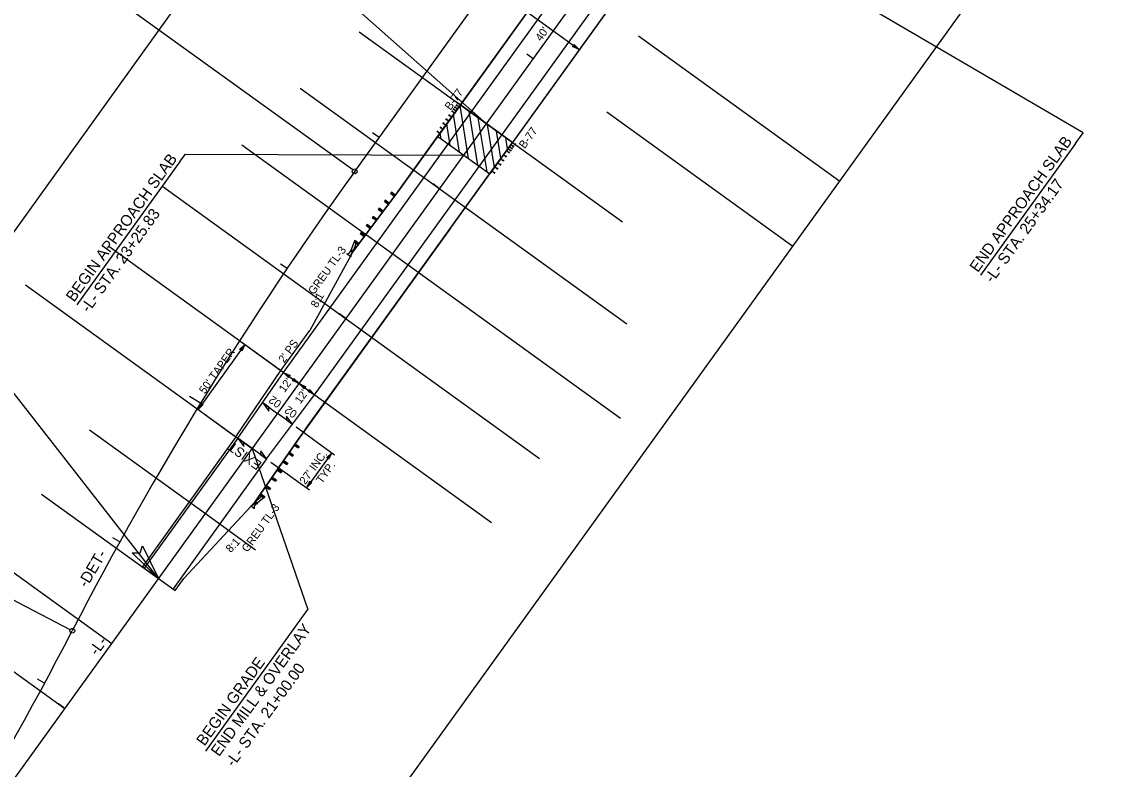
# Model space of a CAD drawing. Extents: x 2189281 to 2191267, y 386656 to 389012.
# Drawn here: x 2190029 to 2190710, y 387465 to 387932 of the extents above; entities that cross this region are included whole.
import ezdxf

# ---------------------------------------------------------------- set-up
doc = ezdxf.new("R2010")
doc.units = 0
for name, color, linetype in [('Prop Approach Slab', 7, 'Continuous'), ('Prop Approach Slab Hatching', 7, 'Continuous'), ('Prop Conc Shoulder Berm Gutter', 7, 'Continuous'), ('Prop Dimension', 7, 'Continuous'), ('Prop Dimension Text', 7, 'Continuous'), ('Prop DSN Text', 7, 'Continuous'), ('Prop EOT', 7, 'Continuous'), ('Prop Guardrail', 7, 'Continuous'), ('Prop Guardrail Anchor Unit CELL', 7, 'Continuous'), ('Prop Horizontal Alignment', 7, 'Continuous'), ('Prop Horizontal Alignment Station Label', 7, 'Continuous'), ('Prop Horizontal Alignment Tick Large', 7, 'Continuous'), ('Prop Horizontal Alignment Tick Small', 7, 'Continuous'), ('Prop Paved Shoulder', 7, 'Continuous'), ('Prop Roadway Bridge', 7, 'Continuous'), ('Prop Structure Anchor Unit CELL', 7, 'Continuous'), ('Prop Superelevation  Arrow CELL', 7, 'Continuous'), ('Prop Superelevation Label', 7, 'Continuous'), ('Prop Terminator CELL', 7, 'Continuous'), ('Scratch_Level_5', 7, 'Continuous'), ('Scratch_Level_6', 7, 'Continuous')]:
    doc.layers.add(name, color=color, linetype=linetype)

msp = doc.modelspace()

# ---------------------------------------------------------------- linework, layer by layer
at = {"layer": 'Prop Approach Slab'}
msp.add_lwpolyline([(2190302.81, 387879.77), (2190288.67, 387860.16), (2190321.11, 387836.77), (2190335.25, 387856.37)], close=True, dxfattribs=at)
at = {"layer": 'Prop Approach Slab Hatching'}
for p, q in [((2190307.96, 387846.25), (2190302.58, 387879.46)), ((2190302.23, 387850.38), (2190298.45, 387873.72)), ((2190313.7, 387842.11), (2190308.23, 387875.85)), ((2190319.43, 387837.98), (2190313.97, 387871.72)), ((2190290.76, 387858.66), (2190290.18, 387862.25)), ((2190296.49, 387854.52), (2190294.31, 387867.99)), ((2190324.04, 387840.82), (2190319.7, 387867.58)), ((2190328.17, 387846.56), (2190325.44, 387863.45)), ((2190332.31, 387852.29), (2190331.17, 387859.31))]:
    msp.add_line(p, q, dxfattribs=at)
at = {"layer": 'Prop Conc Shoulder Berm Gutter'}
for p, q in [((2190264.19, 387826.23), (2190288.67, 387860.16)), ((2190206.57, 387677.93), (2190321.11, 387836.77))]:
    msp.add_line(p, q, dxfattribs=at)
at = {"layer": 'Prop Dimension'}
for p, q in [((2190344.62, 387937.74), (2190377.06, 387914.35)), ((2190168.2, 387730.25), (2190138.96, 387689.7)), ((2190166.44, 387731.53), (2190190.07, 387714.48)), ((2190192.31, 387712.87), (2190211.78, 387698.83)), ((2190138.23, 387690.23), (2190161.39, 387673.52)), ((2190200.21, 387678.81), (2190224.26, 387661.47)), ((2190222.51, 387662.74), (2190206.71, 387640.84)), ((2190184.42, 387656.91), (2190208.46, 387639.57))]:
    msp.add_line(p, q, dxfattribs=at)
at = {"layer": 'Prop DSN Text'}
for p, q in [((2190687.03, 387855.75), (2190627.74, 387773.54)), ((2190127.87, 387844.59), (2190063.28, 387755.03)), ((2190114.3, 387584.19), (2189951.78, 387791.94)), ((2190172.8, 387665.3), (2190207.49, 387564.83)), ((2190143.55, 387624.74), (2190174.85, 387602.17)), ((2190143.71, 387476.39), (2190207.49, 387564.83))]:
    msp.add_line(p, q, dxfattribs=at)
for points in [[(2190687.03, 387855.75), (2190691.85, 387862.42), (2190426.76, 388017.45)], [(2190204.99, 387981.41), (2190199.63, 387973.98), (2190319.03, 387868.07)], [(2190127.87, 387844.59), (2190131.05, 387849), (2190304.89, 387848.46)]]:
    msp.add_lwpolyline(points, dxfattribs=at)
at = {"layer": 'Prop EOT'}
for p, q in [((2190192.31, 387712.87), (2190484.78, 388118.41)), ((2190163.83, 387671.76), (2190192.31, 387712.87)), ((2190163.83, 387671.76), (2190105.39, 387590.62)), ((2190181.76, 387658.83), (2190162.56, 387672.68)), ((2190172.8, 387665.3), (2190172.8, 387665.3)), ((2190181.76, 387658.83), (2190123.31, 387577.7)), ((2190104.17, 387591.49), (2190124.72, 387576.68))]:
    msp.add_line(p, q, dxfattribs=at)
msp.add_lwpolyline([(2190181.76, 387658.83), (2190211.78, 387698.83), (2190504.24, 388104.37), (2190532.84, 388145.39)], dxfattribs=at)
at = {"layer": 'Prop Guardrail'}
msp.add_line((2190335.25, 387856.37), (2190335.26, 387856.36), dxfattribs=at)
for points in [[(2190289.43, 387861.21), (2190263.67, 387825.52)], [(2190201.05, 387670.29), (2190320.63, 387836.09), (2190321.87, 387837.82)]]:
    msp.add_lwpolyline(points, dxfattribs=at)
at = {"layer": 'Prop Guardrail Anchor Unit CELL'}
for p, q in [((2190263.67, 387825.52), (2190235.57, 387788.15)), ((2190259.75, 387825.29), (2190259.15, 387824.49)), ((2190261.54, 387822.69), (2190259.15, 387824.49)), ((2190259.15, 387824.49), (2190260.94, 387824.39)), ((2190262.14, 387823.49), (2190259.75, 387825.29)), ((2190260.34, 387823.59), (2190259.75, 387825.29)), ((2190260.94, 387824.39), (2190260.34, 387823.59)), ((2190261.54, 387822.69), (2190260.34, 387823.59)), ((2190260.34, 387823.59), (2190262.14, 387823.49)), ((2190260.94, 387824.39), (2190261.54, 387822.69)), ((2190262.14, 387823.49), (2190261.54, 387822.69)), ((2190252.13, 387815.25), (2190251.53, 387814.45)), ((2190254.57, 387813.41), (2190252.13, 387815.25)), ((2190252.75, 387813.53), (2190252.13, 387815.25)), ((2190255.92, 387820.29), (2190255.32, 387819.49)), ((2190257.76, 387817.65), (2190255.32, 387819.49)), ((2190255.32, 387819.49), (2190257.14, 387819.37)), ((2190258.36, 387818.45), (2190255.92, 387820.29)), ((2190256.54, 387818.57), (2190255.92, 387820.29)), ((2190257.14, 387819.37), (2190256.54, 387818.57)), ((2190258.36, 387818.45), (2190256.54, 387818.57)), ((2190257.14, 387819.37), (2190257.76, 387817.65)), ((2190248.36, 387810.2), (2190247.76, 387809.4)), ((2190250.18, 387807.58), (2190247.76, 387809.4)), ((2190247.76, 387809.4), (2190249.57, 387809.29)), ((2190250.78, 387808.38), (2190248.36, 387810.2)), ((2190248.97, 387808.49), (2190248.36, 387810.2)), ((2190249.57, 387809.29), (2190248.97, 387808.49)), ((2190250.78, 387808.38), (2190248.97, 387808.49)), ((2190249.57, 387809.29), (2190250.18, 387807.58)), ((2190250.78, 387808.38), (2190250.18, 387807.58)), ((2190253.97, 387812.62), (2190251.53, 387814.45)), ((2190251.53, 387814.45), (2190253.35, 387814.33)), ((2190253.35, 387814.33), (2190252.75, 387813.53)), ((2190254.57, 387813.41), (2190252.75, 387813.53)), ((2190253.35, 387814.33), (2190253.97, 387812.62)), ((2190244.49, 387805.23), (2190243.89, 387804.43)), ((2190246.39, 387802.54), (2190243.89, 387804.43)), ((2190243.89, 387804.43), (2190245.74, 387804.29)), ((2190247, 387803.34), (2190244.49, 387805.23)), ((2190245.14, 387803.49), (2190244.49, 387805.23)), ((2190245.74, 387804.29), (2190245.14, 387803.49)), ((2190247, 387803.34), (2190245.14, 387803.49)), ((2190245.74, 387804.29), (2190246.39, 387802.54)), ((2190236.37, 387794.31), (2190234.67, 387789.46)), ((2190236.97, 387795.11), (2190236.37, 387794.31)), ((2190238.82, 387792.47), (2190236.37, 387794.31)), ((2190236.37, 387794.31), (2190238.2, 387794.19)), ((2190239.42, 387793.27), (2190236.97, 387795.11)), ((2190237.59, 387793.39), (2190236.97, 387795.11)), ((2190238.2, 387794.19), (2190237.59, 387793.39)), ((2190238.2, 387794.19), (2190238.82, 387792.47)), ((2190240.81, 387800.11), (2190240.21, 387799.31)), ((2190242.61, 387797.51), (2190240.21, 387799.31)), ((2190240.21, 387799.31), (2190242.01, 387799.21)), ((2190243.21, 387798.31), (2190240.81, 387800.11)), ((2190241.41, 387798.41), (2190240.81, 387800.11)), ((2190242.01, 387799.21), (2190241.41, 387798.41)), ((2190243.21, 387798.31), (2190241.41, 387798.41)), ((2190242.01, 387799.21), (2190242.61, 387797.51)), ((2190233.3, 387787.23), (2190234.5, 387788.89)), ((2190234.67, 387789.46), (2190234.07, 387788.66)), ((2190235.27, 387787.75), (2190234.07, 387788.66)), ((2190234.07, 387788.66), (2190235.87, 387788.55)), ((2190235.49, 387788.17), (2190234.29, 387786.52)), ((2190234.67, 387789.46), (2190234.37, 387789.06)), ((2190234.5, 387788.89), (2190235, 387788.53)), ((2190235.87, 387788.55), (2190234.67, 387789.46)), ((2190235.27, 387787.75), (2190234.67, 387789.46)), ((2190235, 387788.53), (2190235.49, 387788.17)), ((2190237.59, 387793.39), (2190235.87, 387788.55)), ((2190239.42, 387793.27), (2190237.59, 387793.39)), ((2190231.92, 387786.78), (2190233.3, 387787.23)), ((2190234.3, 387785.06), (2190231.92, 387786.78)), ((2190234.29, 387786.52), (2190234.3, 387785.06)), ((2190201.05, 387670.29), (2190174.46, 387631.84)), ((2190199.6, 387668.2), (2190199.03, 387667.38)), ((2190199.03, 387667.38), (2190201.5, 387665.67)), ((2190199.03, 387667.38), (2190200.26, 387666.53)), ((2190200.83, 387667.35), (2190199.03, 387667.38)), ((2190199.6, 387668.2), (2190202.07, 387666.5)), ((2190200.26, 387666.53), (2190199.6, 387668.2)), ((2190200.83, 387667.35), (2190200.26, 387666.53)), ((2190200.26, 387666.53), (2190202.07, 387666.5)), ((2190201.5, 387665.67), (2190200.83, 387667.35)), ((2190202.07, 387666.5), (2190201.5, 387665.67)), ((2190195.45, 387662.2), (2190197.96, 387660.46)), ((2190197.27, 387662.15), (2190195.45, 387662.2)), ((2190196.02, 387663.02), (2190198.53, 387661.28)), ((2190196.02, 387663.02), (2190196.7, 387661.33)), ((2190197.27, 387662.15), (2190196.7, 387661.33)), ((2190196.7, 387661.33), (2190198.53, 387661.28)), ((2190197.96, 387660.46), (2190197.27, 387662.15)), ((2190198.53, 387661.28), (2190197.96, 387660.46)), ((2190188.85, 387652.65), (2190188.28, 387651.83)), ((2190188.28, 387651.83), (2190190.78, 387650.1)), ((2190190.1, 387651.79), (2190188.28, 387651.83)), ((2190188.85, 387652.65), (2190191.35, 387650.93)), ((2190188.85, 387652.65), (2190189.53, 387650.97)), ((2190190.1, 387651.79), (2190189.53, 387650.97)), ((2190190.78, 387650.1), (2190190.1, 387651.79)), ((2190191.86, 387657.01), (2190194.37, 387655.28)), ((2190193.69, 387656.97), (2190191.86, 387657.01)), ((2190192.43, 387657.84), (2190194.94, 387656.1)), ((2190192.43, 387657.84), (2190193.12, 387656.15)), ((2190193.69, 387656.97), (2190193.12, 387656.15)), ((2190193.12, 387656.15), (2190194.94, 387656.1)), ((2190194.37, 387655.28), (2190193.69, 387656.97)), ((2190194.94, 387656.1), (2190194.37, 387655.28)), ((2190184.7, 387646.65), (2190187.28, 387644.86)), ((2190186.56, 387646.58), (2190184.7, 387646.65)), ((2190185.27, 387647.47), (2190187.85, 387645.69)), ((2190185.27, 387647.47), (2190185.99, 387645.76)), ((2190186.56, 387646.58), (2190185.99, 387645.76)), ((2190185.99, 387645.76), (2190187.85, 387645.69)), ((2190187.28, 387644.86), (2190186.56, 387646.58)), ((2190187.85, 387645.69), (2190187.28, 387644.86)), ((2190189.53, 387650.97), (2190191.35, 387650.93)), ((2190191.35, 387650.93), (2190190.78, 387650.1)), ((2190181.12, 387641.46), (2190183.58, 387639.76)), ((2190182.92, 387641.43), (2190181.12, 387641.46)), ((2190181.68, 387642.29), (2190184.15, 387640.58)), ((2190181.68, 387642.29), (2190182.35, 387640.61)), ((2190182.92, 387641.43), (2190182.35, 387640.61)), ((2190182.35, 387640.61), (2190184.15, 387640.58)), ((2190183.58, 387639.76), (2190182.92, 387641.43)), ((2190184.15, 387640.58), (2190183.58, 387639.76)), ((2190174.5, 387631.77), (2190173.31, 387630.11)), ((2190174.18, 387631.43), (2190175.41, 387630.57)), ((2190174.18, 387631.43), (2190175.98, 387631.4)), ((2190174.3, 387629.39), (2190175.5, 387631.06)), ((2190175, 387631.41), (2190174.5, 387631.77)), ((2190178.79, 387635.41), (2190174.75, 387632.25)), ((2190174.75, 387632.25), (2190175.98, 387631.4)), ((2190175.41, 387630.57), (2190174.75, 387632.25)), ((2190175.5, 387631.06), (2190175, 387631.41)), ((2190175.98, 387631.4), (2190175.41, 387630.57)), ((2190175.98, 387631.4), (2190175.69, 387630.98)), ((2190180.05, 387634.54), (2190175.98, 387631.4)), ((2190177.53, 387636.28), (2190180.05, 387634.54)), ((2190179.36, 387636.23), (2190177.53, 387636.28)), ((2190178.1, 387637.1), (2190180.62, 387635.36)), ((2190178.1, 387637.1), (2190178.79, 387635.41)), ((2190179.36, 387636.23), (2190178.79, 387635.41)), ((2190178.79, 387635.41), (2190180.62, 387635.36)), ((2190180.05, 387634.54), (2190179.36, 387636.23)), ((2190180.62, 387635.36), (2190180.05, 387634.54)), ((2190173.31, 387630.11), (2190171.92, 387629.65)), ((2190171.92, 387629.65), (2190174.31, 387627.94)), ((2190174.31, 387627.94), (2190174.3, 387629.39))]:
    msp.add_line(p, q, dxfattribs=at)
at = {"layer": 'Prop Horizontal Alignment'}
for p, q in [((2189529.37, 386773.11), (2190699.23, 388395.27)), ((2190236.81, 387838.31), (2190392.46, 388054.13))]:
    msp.add_line(p, q, dxfattribs=at)
for centre, start, end in [((2192102.3, 386492.96), 144.20184, 152.59586), ((2188018.5, 388610.18), 324.20184, 332.59586)]:
    msp.add_arc(centre, 2300, start, end, dxfattribs=at)
at = {"layer": 'Prop Horizontal Alignment Station Label'}
for p, q in [((2190235.59, 387839.18), (2190080.89, 387950.75)), ((2190059.07, 387552.26), (2189924.38, 387622.09))]:
    msp.add_line(p, q, dxfattribs=at)
for centre in [(2190236.81, 387838.31), (2190060.4, 387551.57)]:
    msp.add_circle(centre, 1.5, dxfattribs=at)
at = {"layer": 'Prop Horizontal Alignment Tick Large'}
for p, q in [((2190140.51, 387693.54), (2190133.69, 387697.71)), ((2190114.3, 387584.19), (2190107.81, 387588.87))]:
    msp.add_line(p, q, dxfattribs=at)
at = {"layer": 'Prop Horizontal Alignment Tick Small'}
for p, q in [((2190348.28, 387908.62), (2190344.22, 387911.55)), ((2190252.07, 387859.46), (2190248.01, 387862.39)), ((2190289.78, 387827.51), (2190285.73, 387830.44)), ((2190194.55, 387777.67), (2190190.4, 387780.46)), ((2190231.29, 387746.41), (2190227.23, 387749.33)), ((2190172.8, 387665.3), (2190168.74, 387668.22)), ((2190090.18, 387607.13), (2190085.81, 387609.56)), ((2190043.13, 387518.9), (2190038.73, 387521.27)), ((2190055.81, 387503.08), (2190051.75, 387506.01))]:
    msp.add_line(p, q, dxfattribs=at)
at = {"layer": 'Prop Paved Shoulder'}
for p, q in [((2190411.02, 388029.82), (2190288.67, 387860.16)), ((2190443.46, 388006.42), (2190321.11, 387836.77)), ((2190264.19, 387826.23), (2190235.57, 387788.15)), ((2190235.57, 387788.15), (2190208.71, 387739.03)), ((2190162.56, 387672.68), (2190137.23, 387637.3)), ((2190137.23, 387637.3), (2190104.17, 387591.49)), ((2190174.46, 387631.84), (2190130.07, 387584.11)), ((2190124.72, 387576.68), (2190130.07, 387584.11))]:
    msp.add_line(p, q, dxfattribs=at)
for points in [[(2190296.64, 387802.83), (2190201.05, 387670.29), (2190174.46, 387631.84)], [(2190162.56, 387672.68), (2190190.69, 387714.04), (2190208.71, 387739.03)]]:
    msp.add_lwpolyline(points, dxfattribs=at)
at = {"layer": 'Prop Roadway Bridge'}
msp.add_lwpolyline([(2190302.81, 387879.77), (2190396.4, 388009.54), (2190428.84, 387986.14), (2190335.25, 387856.37)], close=True, dxfattribs=at)
at = {"layer": 'Prop Structure Anchor Unit CELL'}
for p, q in [((2190302.81, 387879.77), (2190289.43, 387861.21)), ((2190297.86, 387876.33), (2190297.19, 387875.4)), ((2190298.78, 387877.6), (2190298.11, 387876.67)), ((2190300.07, 387875.97), (2190298.44, 387877.14)), ((2190299.69, 387878.87), (2190299.02, 387877.94)), ((2190300.98, 387877.23), (2190299.36, 387878.4)), ((2190300.61, 387880.13), (2190299.94, 387879.21)), ((2190301.89, 387878.5), (2190300.27, 387879.67)), ((2190301.52, 387881.4), (2190300.85, 387880.47)), ((2190302.81, 387879.77), (2190301.18, 387880.94)), ((2190294.21, 387871.26), (2190293.54, 387870.33)), ((2190295.5, 387869.63), (2190293.87, 387870.8)), ((2190296.04, 387873.8), (2190295.37, 387872.87)), ((2190297.32, 387872.16), (2190295.7, 387873.33)), ((2190299.15, 387874.7), (2190297.53, 387875.87)), ((2190288.72, 387863.66), (2190288.05, 387862.73)), ((2190290.01, 387862.02), (2190288.39, 387863.19)), ((2190290.55, 387866.19), (2190289.88, 387865.26)), ((2190291.84, 387864.56), (2190290.22, 387865.73)), ((2190292.38, 387868.73), (2190291.71, 387867.8)), ((2190293.67, 387867.09), (2190292.05, 387868.26)), ((2190335.25, 387856.37), (2190321.87, 387837.82)), ((2190335.25, 387856.37), (2190336.87, 387855.2)), ((2190337.21, 387855.66), (2190336.54, 387854.74)), ((2190329.77, 387848.77), (2190331.39, 387847.6)), ((2190331.59, 387851.3), (2190333.22, 387850.13)), ((2190332.51, 387852.57), (2190334.13, 387851.4)), ((2190333.55, 387850.6), (2190332.88, 387849.67)), ((2190333.42, 387853.84), (2190335.04, 387852.67)), ((2190334.47, 387851.86), (2190333.8, 387850.93)), ((2190334.34, 387855.1), (2190335.96, 387853.93)), ((2190335.38, 387853.13), (2190334.71, 387852.2)), ((2190336.29, 387854.4), (2190335.62, 387853.47)), ((2190326.11, 387843.7), (2190327.73, 387842.53)), ((2190328.07, 387842.99), (2190327.4, 387842.06)), ((2190327.94, 387846.23), (2190329.56, 387845.06)), ((2190329.9, 387845.53), (2190329.23, 387844.6)), ((2190331.72, 387848.06), (2190331.05, 387847.13)), ((2190322.45, 387838.63), (2190324.08, 387837.46)), ((2190324.41, 387837.92), (2190323.74, 387836.99)), ((2190324.28, 387841.16), (2190325.91, 387839.99)), ((2190326.24, 387840.46), (2190325.57, 387839.53))]:
    msp.add_line(p, q, dxfattribs=at)
at = {"layer": 'Prop Superelevation  Arrow CELL'}
for p, q in [((2190179.39, 387693.83), (2190188.59, 387687.2)), ((2190197.97, 387680.43), (2190188.59, 387687.2)), ((2190163.83, 387671.76), (2190173.56, 387664.74)), ((2190181.76, 387658.83), (2190172.03, 387665.85))]:
    msp.add_line(p, q, dxfattribs=at)
for points in [[(2190179.39, 387693.83), (2190183.09, 387688.7), (2190183.14, 387691.13)], [(2190197.97, 387680.43), (2190194.28, 387685.57), (2190194.22, 387683.14)], [(2190163.83, 387671.76), (2190167.52, 387666.63), (2190167.58, 387669.05)], [(2190181.76, 387658.83), (2190178.07, 387663.96), (2190178.01, 387661.54)]]:
    msp.add_lwpolyline(points, close=True, dxfattribs=at)
at = {"layer": 'Prop Terminator CELL'}
for points in [[(2190373.87, 387917.61), (2190377.06, 387914.35), (2190372.92, 387916.35), (2190373.86, 387916.66)], [(2190164.94, 387727.06), (2190168.2, 387730.25), (2190166.21, 387726.12), (2190165.89, 387727.05)], [(2190195.51, 387709.61), (2190192.31, 387712.87), (2190196.45, 387710.87), (2190195.51, 387710.56)], [(2190195.51, 387709.61), (2190192.31, 387712.87), (2190196.45, 387710.87), (2190195.51, 387710.56)], [(2190198.85, 387709.11), (2190202.04, 387705.85), (2190197.9, 387707.85), (2190198.84, 387708.16)], [(2190205.24, 387702.59), (2190202.04, 387705.85), (2190206.18, 387703.85), (2190205.25, 387703.54)], [(2190208.58, 387702.09), (2190211.78, 387698.83), (2190207.64, 387700.83), (2190208.57, 387701.14)], [(2190208.58, 387702.09), (2190211.78, 387698.83), (2190207.64, 387700.83), (2190208.57, 387701.14)], [(2190142.22, 387692.9), (2190138.96, 387689.7), (2190140.96, 387693.84), (2190141.27, 387692.9)], [(2190219.25, 387659.54), (2190222.51, 387662.74), (2190220.51, 387658.6), (2190220.2, 387659.53)], [(2190209.97, 387644.03), (2190206.71, 387640.84), (2190208.71, 387644.98), (2190209.02, 387644.04)], [(2190104.23, 387604.68), (2190114.3, 387584.19), (2190097.78, 387600.15), (2190102.71, 387600.18)]]:
    msp.add_lwpolyline(points, close=True, dxfattribs=at)
at = {"layer": 'Scratch_Level_5'}
for p, q in [((2189367.15, 386890.09), (2190537.02, 388512.26)), ((2189691.59, 386656.12), (2190861.45, 388278.29)), ((2190239.58, 387925.36), (2190404.06, 387806.75)), ((2190414, 387922.87), (2190539.74, 387832.19)), ((2190202.73, 387890.29), (2190406.72, 387743.18)), ((2190394.19, 387875.51), (2190510.49, 387791.64)), ((2190166.36, 387854.87), (2190402.84, 387684.33)), ((2190116.87, 387828.92), (2190352.24, 387659.18)), ((2190083.23, 387791.54), (2190322.33, 387619.1)), ((2190031.18, 387767.43), (2190172.8, 387665.3)), ((2190071.13, 387676.97), (2190143.55, 387624.74)), ((2190041.2, 387636.91), (2190114.3, 387584.19)), ((2190011.57, 387596.63), (2190085.06, 387543.64)), ((2189960.07, 387572.12), (2190055.81, 387503.08))]:
    msp.add_line(p, q, dxfattribs=at)
at = {"layer": 'Scratch_Level_6'}
for points in [[(2190235.54, 387788.18), (2190263.66, 387825.52), (2190288.18, 387859.5), (2190302.8, 387879.77)], [(2190174.47, 387631.83), (2190201.05, 387670.29), (2190320.64, 387836.09), (2190335.26, 387856.36)]]:
    msp.add_lwpolyline(points, dxfattribs=at)

# ---------------------------------------------------------------- texts
at = {"layer": 'Prop Dimension Text'}
for s, rotation, p in [("40'", 54.20184, (2190353.19, 387919.12)), ('8:1', 61.33008, (2190213.35, 387752.75)), ("2' PS", 54.20184, (2190192.74, 387718.31)), ("50' TAPER", 54.20184, (2190143.16, 387699.02)), ("12'", 54.20184, (2190193.03, 387699.91)), ("12'", 54.20184, (2190202.88, 387692.8)), ("27' INC.", 54.20184, (2190205.93, 387642.47)), ('TYP.', 54.20184, (2190216.32, 387642.98)), ('8:1', 46.94429, (2190159.33, 387599.95))]:
    msp.add_text(s, height=5, rotation=rotation, dxfattribs=at).set_placement(p)
at = {"layer": 'Prop DSN Text'}
for s, rotation, p in [('END APPROACH SLAB', 54.20184, (2190625.97, 387774.82)), ('BEGIN APPROACH SLAB', 54.20184, (2190061.51, 387756.31)), ('-L- STA. 25+34.17', 54.20184, (2190635.19, 387768.17)), ('-L- STA. 23+25.83', 54.20184, (2190070.73, 387749.66)), ('-DET-', 59.42784, (2190069.43, 387577.96)), ('END MILL & OVERLAY', 54.05966, (2190152.06, 387472.63)), ('-L-', 54.20184, (2190075.92, 387535.6)), ('BEGIN GRADE', 54.05966, (2190142.99, 387479.2)), ('-L- STA. 21+00.00', 54.05966, (2190161.13, 387466.06))]:
    msp.add_text(s, height=7, rotation=rotation, dxfattribs=at).set_placement(p)
at = {"layer": 'Prop Guardrail Anchor Unit CELL'}
for s, p in [('B-77', (2190296.62, 387876.1)), ('B-77', (2190342.97, 387852.13)), ('GREU TL-3', (2190211.35, 387760.93)), ('GREU TL-3', (2190169.77, 387600.2))]:
    msp.add_text(s, height=5, rotation=54.20184, dxfattribs=at).set_placement(p)
at = {"layer": 'Prop Superelevation Label'}
for s, height, p in [('02', 5, (2190191.51, 387694.27)), ('02', 5, (2190201.34, 387687.96)), ('EXIST', 6, (2190179.3, 387656.32))]:
    msp.add_text(s, height=height, rotation=144.22704, dxfattribs=at).set_placement(p)

doc.saveas('drawing.dxf')
